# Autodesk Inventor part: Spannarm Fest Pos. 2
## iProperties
Created: 2009-11
Part Number: Spannarm Fest Pos. 2
Document SubType Name: Modeling
Designer: user
Author: user
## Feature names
1. Extrusion1
2. Bohrung2 [Hole]
3. Extrusion2
4. Rundung1 [Fillet]
5. Bohrung3 [Hole]
6. Extrusion4
7. Bohrung4 [Hole]
